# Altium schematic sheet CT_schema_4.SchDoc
size 454 x 430 mm
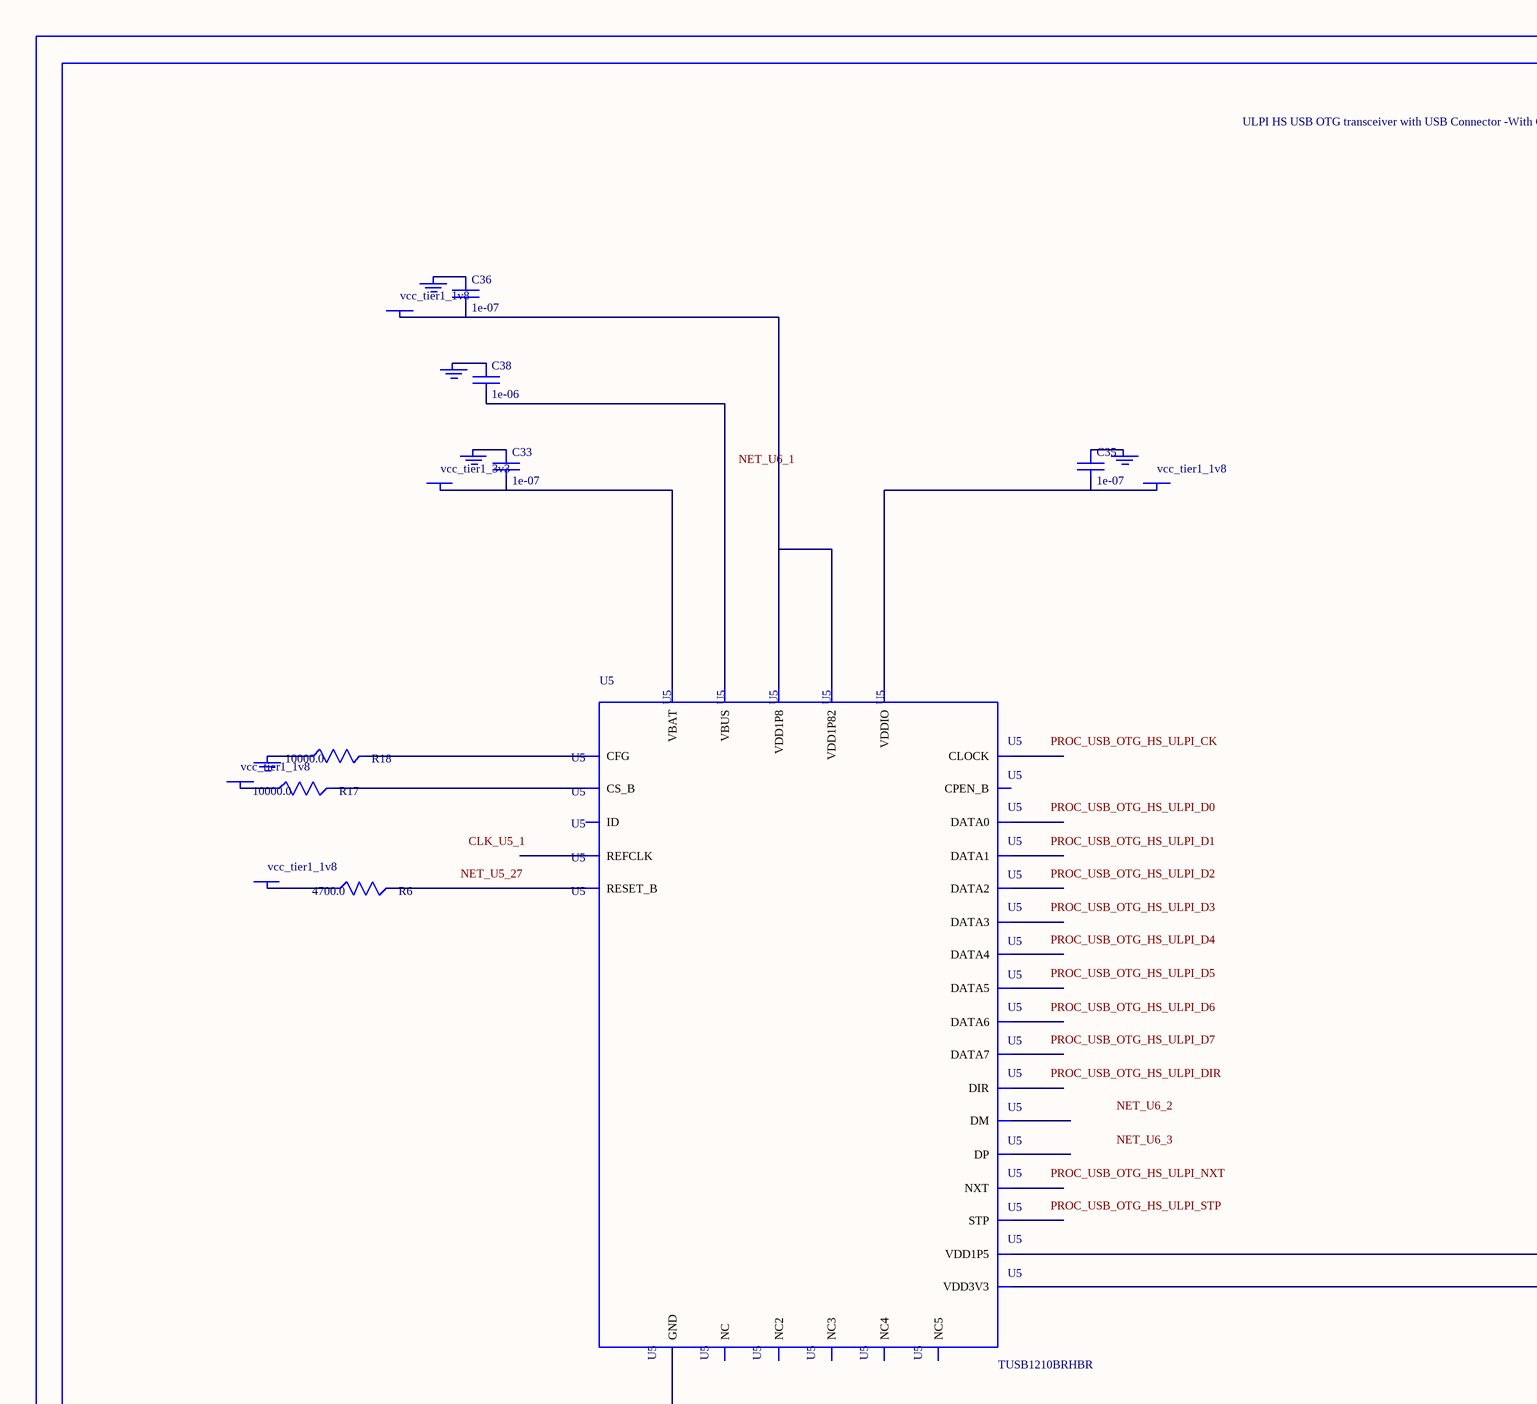
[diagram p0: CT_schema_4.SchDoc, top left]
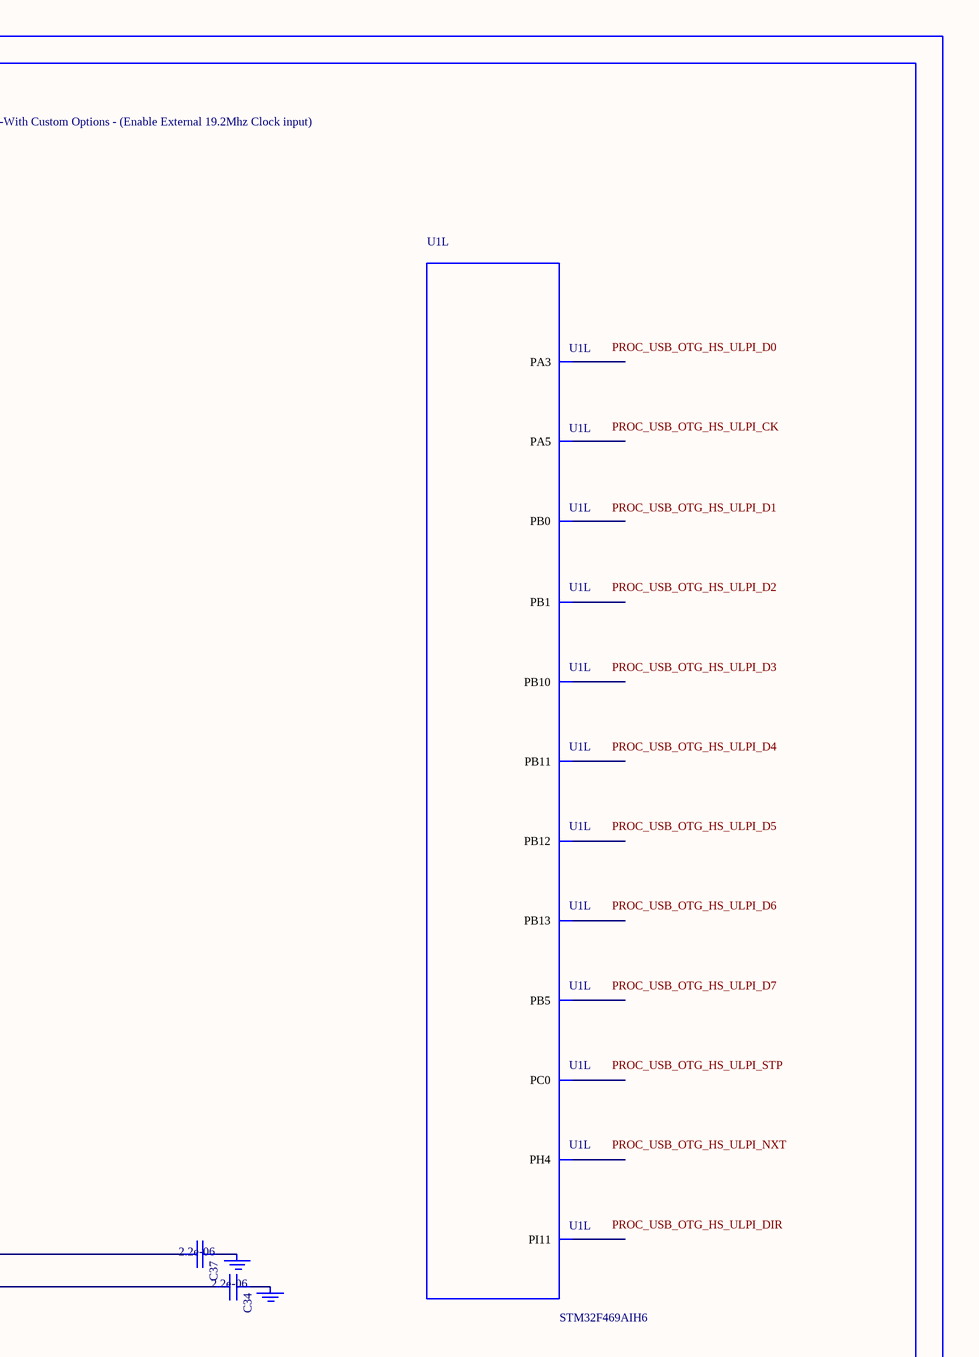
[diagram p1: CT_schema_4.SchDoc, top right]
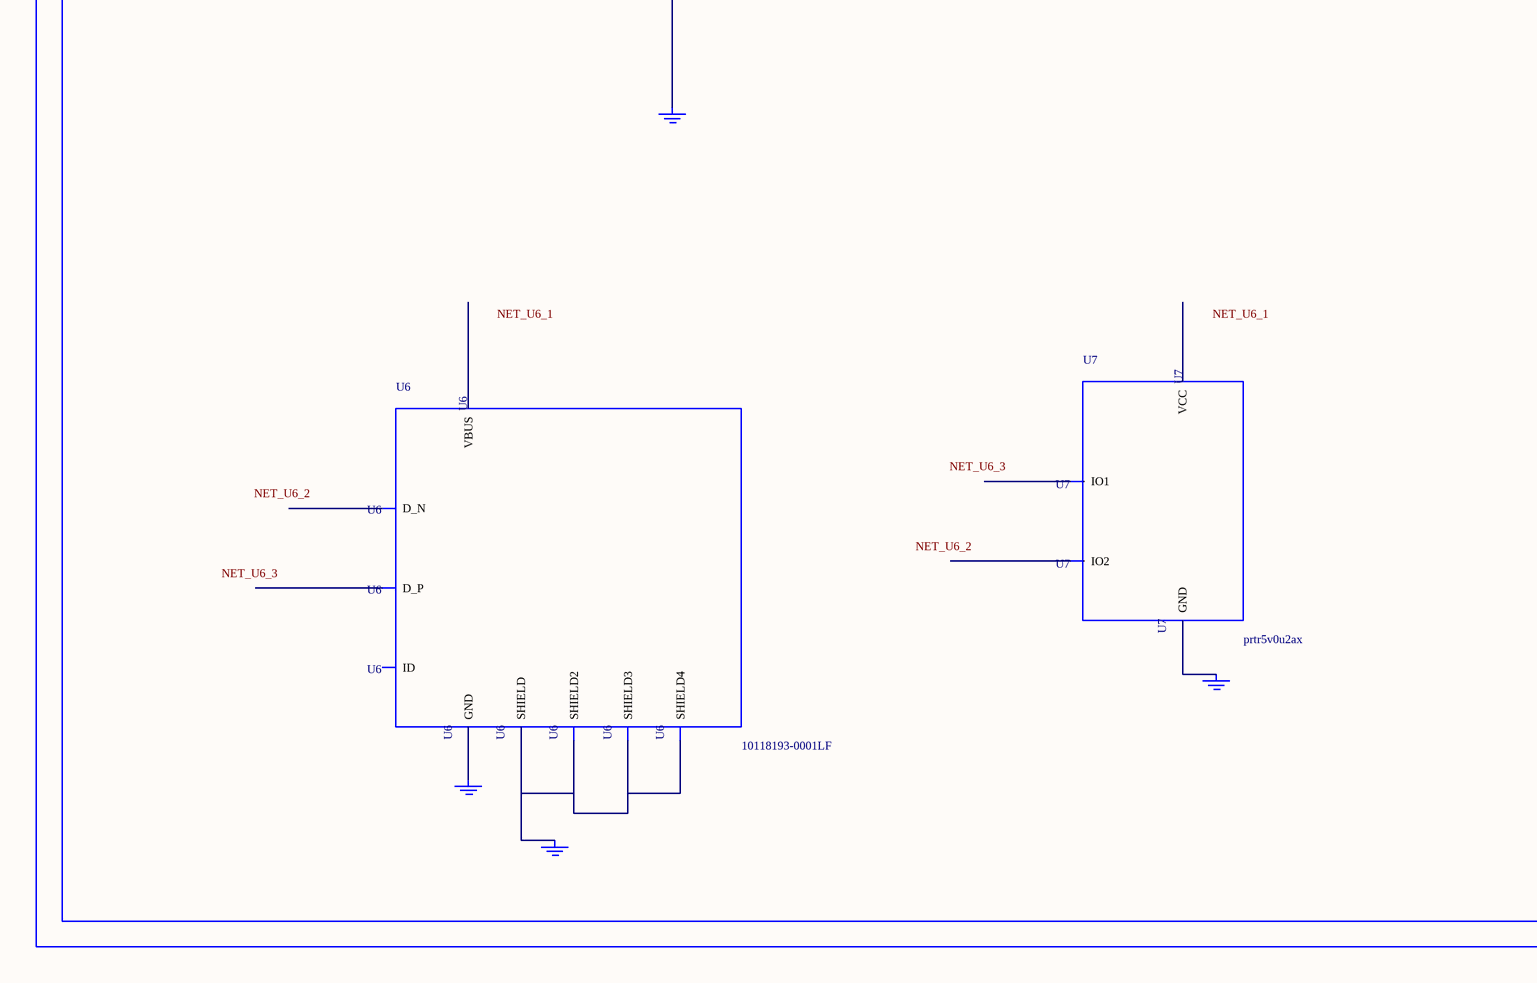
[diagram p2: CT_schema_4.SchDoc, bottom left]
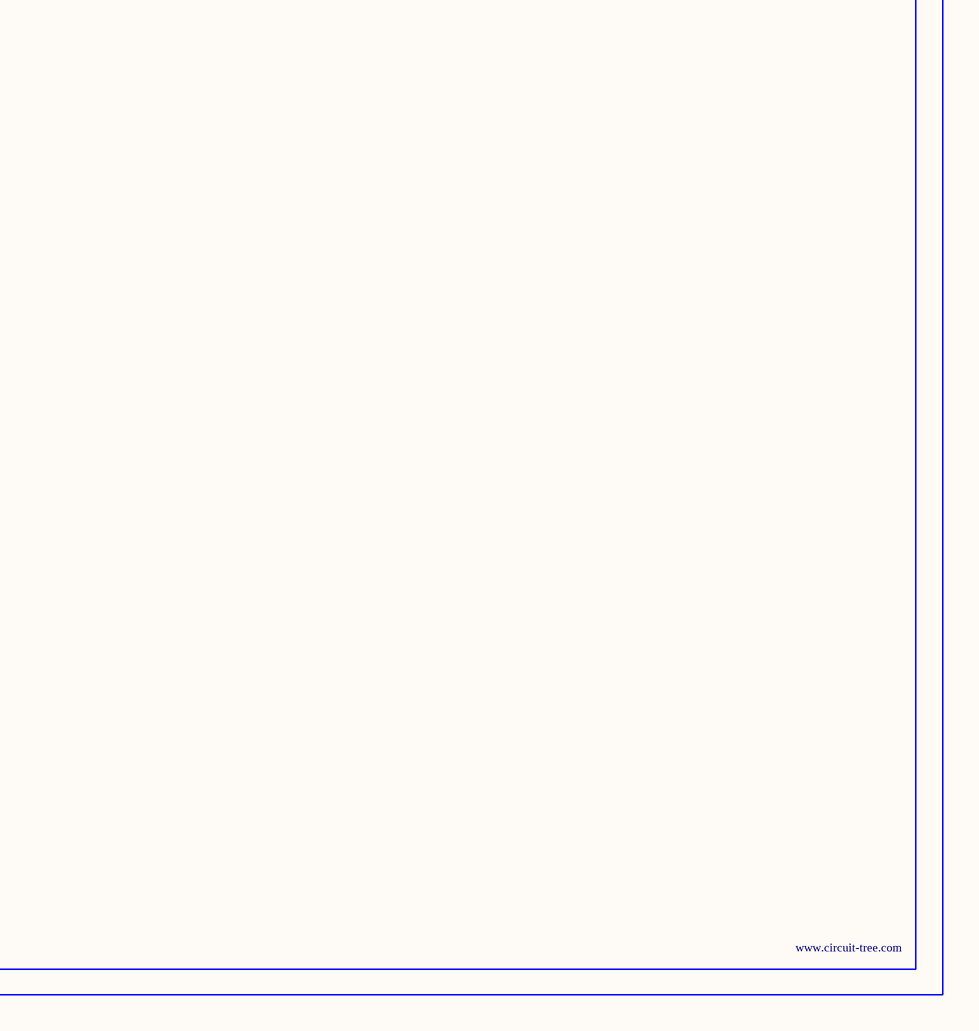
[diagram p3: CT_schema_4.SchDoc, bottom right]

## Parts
BORDER3  (no value)
C33  1e-07  [C0402]
C34  2.2e-06  [C0603]
C35  1e-07  [C0402]
C36  1e-07  [C0402]
C37  2.2e-06  [C0603]
C38  1e-06  [C0603]
GND_INSTANCE_3_0  (no value)
GND_INSTANCE_3_1  (no value)
GND_INSTANCE_3_2  (no value)
GND_INSTANCE_3_3  (no value)
GND_INSTANCE_3_4  (no value)
GND_INSTANCE_3_5  (no value)
GND_INSTANCE_3_6  (no value)
GND_INSTANCE_3_7  (no value)
GND_INSTANCE_3_8  (no value)
GND_INSTANCE_3_9  (no value)
GND_INSTANCE_3_10  (no value)
POWER_INSTANCE_3_0  vcc_tier1_1v8
POWER_INSTANCE_3_1  vcc_tier1_3v3
POWER_INSTANCE_3_2  vcc_tier1_1v8
POWER_INSTANCE_3_3  vcc_tier1_1v8
POWER_INSTANCE_3_4  vcc_tier1_1v8
R6  4700.0  [R0603]
R17  10000.0  [R0603]
R18  10000.0  [R0603]
U1  STM32F469AIH6  [UFBGA169]  (part L of 13)
U5  TUSB1210BRHBR  [RHB32_3P45X3P45]
U6  10118193-0001LF  [FCI_10118193-0001LF]
U7  prtr5v0u2ax  [SOT143B]

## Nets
NetC33_1: C33.1 GND_INSTANCE_3_3.0(GND)
NetC33_2: C33.2 POWER_INSTANCE_3_1.0(PWR) U5.21(VBAT)
NetC34_1: C34.1 GND_INSTANCE_3_2.0(GND)
NetC34_2: C34.2 U5.20(VDD3V3)
NetC35_1: C35.1 GND_INSTANCE_3_6.0(GND)
NetC35_2: C35.2 POWER_INSTANCE_3_3.0(PWR) U5.32(VDDIO)
NetC36_1: C36.1 GND_INSTANCE_3_5.0(GND)
NetC36_2: C36.2 POWER_INSTANCE_3_2.0(PWR) U5.28(VDD1P8) U5.30(VDD1P82)
NetC37_1: C37.1 GND_INSTANCE_3_0.0(GND)
NetC37_2: C37.2 U5.12(VDD1P5)
NetC38_1: C38.1 GND_INSTANCE_3_4.0(GND)
NetC38_2: C38.2 U5.22(VBUS)
NetGND_INSTANCE_3_1_0: GND_INSTANCE_3_1.0(GND) R18.1
NetGND_INSTANCE_3_7_0: GND_INSTANCE_3_7.0(GND) U5.33(GND)
NetGND_INSTANCE_3_8_0: GND_INSTANCE_3_8.0(GND) U6.6(SHIELD) U6.7(SHIELD2) U6.8(SHIELD3) U6.9(SHIELD4)
NetGND_INSTANCE_3_9_0: GND_INSTANCE_3_9.0(GND) U6.5(GND)
NetGND_INSTANCE_3_10_0: GND_INSTANCE_3_10.0(GND) U7.1(GND)
NetPOWER_INSTANCE_3_0_0: POWER_INSTANCE_3_0.0(PWR) R17.1
NetPOWER_INSTANCE_3_4_0: POWER_INSTANCE_3_4.0(PWR) R6.1
NetR6_2: R6.2 U5.27(RESET_B)
NetR17_2: R17.2 U5.11(CS_B)
NetR18_2: R18.2 U5.14(CFG)

Not connected (* = marked no-connect by the designer): U1 D5(PB5) F2(PI11) K3(PA3) K5(PB1) M1(PC0) M2(PH4) M3(PA5) M8(PB10) N4(PB0) N8(PB11) N10(PB12) N11(PB13); U5 1(REFCLK) 2(NXT) 3(DATA0) 4(DATA1) 5(DATA2) 6(DATA3) 7(DATA4) 8(NC) 9(DATA5) 10(DATA6) 13(DATA7) 15(NC2) 16(NC3) 17(CPEN_B) 18(DP) 19(DM) 23(ID) 24(NC4) 25(NC5) 26(CLOCK) 29(STP) 31(DIR); U6 1(VBUS) 2(D_N) 3(D_P) 4(ID); U7 2(IO1) 3(IO2) 4(VCC)

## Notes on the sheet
- Labels drawn without touching a wire or pin: CLK_U5_1, NET_U5_27, NET_U6_1, NET_U6_2, NET_U6_3, PROC_USB_OTG_HS_ULPI_CK, PROC_USB_OTG_HS_ULPI_D0, PROC_USB_OTG_HS_ULPI_D1, PROC_USB_OTG_HS_ULPI_D2, PROC_USB_OTG_HS_ULPI_D3, PROC_USB_OTG_HS_ULPI_D4, PROC_USB_OTG_HS_ULPI_D5, PROC_USB_OTG_HS_ULPI_D6, PROC_USB_OTG_HS_ULPI_D7, PROC_USB_OTG_HS_ULPI_DIR, PROC_USB_OTG_HS_ULPI_NXT, PROC_USB_OTG_HS_ULPI_STP

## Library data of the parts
BORDER3 = BORDER_PAGE3
C33 C35 C36 = C0402C104K3RACTU
C34 C37 = C0603C225K8RACTU
C38 = C0603C105K3RACTU
GND_INSTANCE_3_0-GND_INSTANCE_3_10 = GND
POWER_INSTANCE_3_0-POWER_INSTANCE_3_4 = PWR
R6 = RC0603JR-074K7L
R17 R18 = RC0603JR-0710KL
